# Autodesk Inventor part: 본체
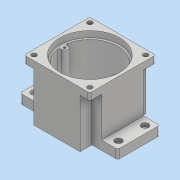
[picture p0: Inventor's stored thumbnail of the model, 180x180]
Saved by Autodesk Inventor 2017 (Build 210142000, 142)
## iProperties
Part Number: 본체
Material: 일반
Document SubType Name: Modeling
Designer: user
Density: 1 g/cm^3
Appearance: 기본값
Mass: 324.711 g
Surface Area: 795.5 cm^2
Volume: 324.711 cm^3
Author: user
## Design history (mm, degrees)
sketch "스케치1"
  geometry: L1 (0, 0)-(140, 0); L2 (0, 0)-(0, 60); L3 (0, 60)-(140, 60); L4 (140, 60)-(140, 0)
  constraints: 8 end point, 1 horizontal, 1 perpendicular, 1 vertical
  dimensions: "d0" = 140 distance of L1.start L1.end; "d4" = 60 distance of L1.start L2.end; "d5" = 140 distance of L2.end L3.end
extrude "돌출1" new body sketch "스케치1" distance "d6" = 13; taper "d7" = 0 deg
sketch "스케치2"
  geometry: L1 (-140, 60)-(0, 60) reference; L2 (-70, 60)-(-70, 0); L3 (0, 0)-(-140, 0) reference; L4 (-140, 30)-(0, 30); L5 (-117, 77)-(-117, -17); L6 (-23, 77)-(-23, -17); L7 (-117, 77)-(-23, 77); L8 (-117, -17)-(-23, -17)
  constraints: 12 end point, 4 parallel, 2 midpoint, 1 horizontal
  dimensions: "d8" = 47 distance between parallel lines of L2 L5; "d9" = 47 distance between parallel lines of L2 L6; "d10" = 47 distance between parallel lines of L4 L7; "d12" = 47 distance between parallel lines of L4 L8
extrude "돌출2" join sketch "스케치2" distance "d13" = 80; taper "d14" = 0 deg
sketch "스케치4"
  geometry: L1 (0, 0)-(-23, 0) reference; L2 (-23, 0)-(-23, -17); L3 (-37, -17)-(-37, 0); L4 (-37, -17)-(-23, -17); L5 (-103, -17)-(-117, -17); L6 (-117, 0)-(-140, 0) reference; L7 (-117, 0)-(-103, 0); L8 (-103, 0)-(-103, -17); L9 (-23, 0)-(-37, 0); L10 (-117, -17)-(-117, 0) reference; L11 (-117, -17)-(-117, 0); L12 (0, 60)-(0, 0) reference; L13 (0, 30)-(-140, 30); L14 (-140, 0)-(-140, 60) reference; L15 (-23, 60)-(-23, 77); L16 (-37, 77)-(-37, 60); L17 (-37, 77)-(-23, 77); L18 (-23, 60)-(-37, 60); L19 (-103, 77)-(-117, 77); L20 (-117, 60)-(-103, 60); L21 (-103, 60)-(-103, 77); L22 (-117, 77)-(-117, 60); L23 (-117, 77)-(-117, 60)
  constraints: 36 end point, 8 symmetric about line, 3 horizontal, 2 midpoint, 2 vertical, 1 collinear
extrude "돌출3" cut sketch "스케치4" distance "d19" = 70; taper "d20" = 0 deg
sketch "스케치7"
  geometry: L1 (37, -17)-(103, -17) reference; L2 (70, -17)-(70, 97.053); L3 (0, 60)-(0, 0) reference; L4 (0, 30)-(150.591, 30); C1 r 43 at (70, 30)
  constraints: 4 end point, 2 midpoint, 2 point on line, 1 centre point, 1 horizontal, 1 vertical
  dimensions: "d26" = 86 diameter of C1
extrude "돌출4" cut sketch "스케치7" distance "d27" = 9; taper "d28" = 0 deg
sketch "스케치8"
  geometry: C1 r 40 at (0, 0); 1 further point
  constraints: 1 centre point
  dimensions: "d29" = 80 diameter of C1
sketch "스케치9"
  geometry: L1 (-117, 77)-(-23, 77) reference; L2 (-70, 77)-(-70, -17); L3 (-23, -17)-(-117, -17) reference; L4 (-140, 0)-(-140, 60) reference; L5 (-140, 30)-(0, 30); L6 (0, 60)-(0, 0) reference; L7 (-70, 30)-(-71, 30); L8 (-70, 30)-(-70, 41); L9 (-70, 30)-(-70, 10); C1 r 27.5 at (-70, 41)
  constraints: 10 end point, 5 midpoint, 3 point on line, 1 centre point, 1 coincident
  dimensions: "d30" = 1 distance of L7.start L7.end; "d31" = 11 distance of L7.start L8.end; "d32" = 20 distance of L7.start L9.end; "d35" = 55 diameter of C1
extrude "돌출5" join sketch "스케치9" distance "d36" = 7; taper "d37" = 0 deg
sketch "스케치10"
  geometry: L1 (-33, 36)-(33, 36) reference; C1 r 27.5 at (0, 0) reference; C2 r 16 at (0, 0); 1 further point
  constraints: 1 centre point, 1 coincident
  dimensions: "d39" = 32 diameter of C2
extrude "돌출6" cut sketch "스케치10" distance "d40" = 8.3; taper "d41" = 0 deg
sketch "스케치11"
  geometry: C1 r 12.5 at (0, 0); 1 further point
  constraints: 1 centre point
  dimensions: "d44" = 25 diameter of C1
extrude "돌출7" cut sketch "스케치11" distance "d45" = 4.7; taper "d46" = 0 deg
sketch "스케치12"
  geometry: C1 r 17.5 at (0, 0); 1 further point
  constraints: 1 centre point
  dimensions: "d47" = 35 diameter of C1
extrude "돌출8" cut sketch "스케치12" distance "d48" = 10; taper "d49" = 0 deg
extrude "돌출9" cut sketch "스케치8" distance "d50" = 62; taper "d51" = 0 deg
node "작업 평면2"
sketch "스케치18"
  geometry: A1 r 40 centre (0, 0) between (-39.279, 7.559) and (-39.279, -7.559) reference; A2 r 4 centre (-36, 0) between (-36.19, -3.995) and (-36.19, 3.995); A3 r 3 centre (-36.333, 6.992) between (-39.279, 7.559) and (-36.19, 3.995); A4 r 3 centre (-36.333, -6.992) between (-36.19, -3.995) and (-39.279, -7.559); A5 r 40 centre (0, 0) between (-39.279, 7.559) and (-39.279, -7.559); 1 further point
  constraints: 10 point on circle, 6 tangent, 4 centre point, 1 horizontal alignment
  dimensions: "d81" = 8 diameter of A2; "d82" = 36 distance of A1.centre A2.centre; "d83" = 3 radius of A3; "d84" = 3 radius of A4
extrude "돌출12" join sketch "스케치18" stored distance "d85" = 7; taper "d86" = 0 deg
sketch "스케치20"
  geometry: L1 (-32, 0)-(-36, 0); A1 r 4 centre (-36, 0) between (-36.19, -3.995) and (-36.19, 3.995) reference; 1 further point
  constraints: 2 end point, 1 horizontal, 1 point on circle
hole "구멍1" sketch "스케치20" at (-36, 0) diameter "d87" = 3.242; stored, may be unused: countersink angle "d91" = 90 deg, drill point angle "d93" = 118 deg; dims "d88" = 7, "d89" = 4, "d90" = 2, "d92" = 9
node "작업 평면1"
chamfer "모따기1" distance "d94" = 0.8; stored, may be unused: second distance "d95" = 2, angle "d96" = 30 deg
sketch "스케치21"
  geometry: C1 r 21 at (0, 11); C2 r 15 at (0, -20); C3 r 17.5 at (0, 11) reference; 1 further point
  constraints: 2 centre point, 1 concentric, 1 vertical alignment
  dimensions: "d97" = 42 diameter of C1; "d98" = 30 diameter of C2; "d101" = 31 distance of C1.centre C2.centre
extrude "돌출13" join sketch "스케치21" distance "d99" = 7; taper "d100" = 0 deg
hole "구멍2" diameter "d104" = 35; stored, may be unused: countersink angle "d108" = 90 deg, drill point angle "d110" = 0 deg; dims "d102" = 10, "d103" = 10, "d105" = 7, "d106" = 4, "d107" = 2, "d109" = 10
hole "구멍3" diameter "d113" = 19; stored, may be unused: countersink angle "d117" = 90 deg, drill point angle "d119" = 0 deg; dims "d111" = 10, "d112" = 10, "d114" = 7, "d115" = 22, "d116" = 7, "d118" = 10
fillet "모깎기1" dims "d120" = 3
chamfer "모따기2" distance "d121" = 1; stored, may be unused: second distance "d122" = 2, angle "d123" = 30 deg
sketch "스케치22"
  geometry: L1 (-117, 77)-(-23, 77) reference; L2 (-70, 77)-(-30, 77); L3 (-23, 77)-(-23, -17) reference; L4 (-23, 30)-(-23, 70); L5 (-23, 70)-(-44.083, 70); L6 (-30, 77)-(-30, 52.8); L7 (-23, 30)-(-140, 30); L8 (-140, 0)-(-140, 60) reference; L9 (-70, 77)-(-70, -17); C1 r 3.5 at (-30, 70); C2 r 3.5 at (-30, -10); C3 r 3.5 at (-110, 70); C4 r 3.5 at (-110, -10); 1 further point
  constraints: 12 end point, 4 centre point, 3 midpoint, 3 point on line, 3 symmetric about line, 2 perpendicular, 2 vertical, 3 other
  dimensions: "d124" = 40 distance of L2.start L2.end; "d125" = 40 distance of L4.start L4.end; "d126" = 7 diameter of C1
extrude "돌출14" cut sketch "스케치22" distance "d127" = 50; taper "d128" = 0 deg
fillet "모깎기2" dims "d129" = 3
sketch "스케치23"
  geometry: L1 (0, 57)-(0, 3) reference; L2 (0, 30)-(0, 49); L3 (0, 49)-(0, 11); L4 (-114, 77)-(-26, 77) reference; L5 (-70, 77)-(-10, 77); L6 (-10, 77)-(-10, -14.148); L7 (0, 49)-(-159.364, 49); L8 (0, 11)-(-172.726, 11); L9 (-70, 77)-(-130, 77); L10 (-130, 77)-(-130, -21.222); C1 r 2.25 at (-130, 49); C2 r 2.25 at (-130, 11); C3 r 2.25 at (-10, 11); C4 r 2.25 at (-10, 49); 1 further point
  constraints: 16 end point, 11 point on line, 4 centre point, 2 horizontal, 2 midpoint, 1 collinear, 1 perpendicular, 1 vertical
  dimensions: "d130" = 19 distance of L2.start L2.end; "d131" = 38 distance of L2.end L3.end; "d132" = 60 distance of L5.start L5.end; "d133" = 60 distance of L5.start L9.end; "d134" = 4.5 diameter of C1; "d135" = 4.5 diameter of C2; "d136" = 4.5 diameter of C3; "d137" = 4.5 diameter of C4
extrude "돌출15" cut sketch "스케치23" distance "d138" = 50; taper "d139" = 0 deg
sketch "스케치24"
  geometry: C1 r 2.25 at (10, 49) reference; C2 r 5 at (10, 49); C3 r 2.25 at (10, 11) reference; C4 r 5 at (10, 11); C5 r 5 at (129.989, 49); C6 r 2.25 at (130, 11) reference; C7 r 5 at (130, 11); 1 further point
  constraints: 4 centre point, 3 coincident
  dimensions: "d140" = 10 diameter of C2; "d141" = 10 diameter of C4; "d142" = 10 diameter of C5; "d143" = 10 diameter of C7
extrude "돌출16" cut sketch "스케치24" distance "d144" = 5; taper "d145" = 0 deg
sketch "스케치25"
  geometry: L1 (77, -80)-(-11, -80) reference; L2 (60.5, 7)-(5.5, 7) reference; L3 (33, -80)-(33, 17.948); 2 further points
  constraints: 2 end point, 1 midpoint, 1 vertical, 1 other
  dimensions: "d146" = 40 distance from line of point (33, -40) L1; "d149" = 0 distance from line of L3 point (33, -40)
feature "엠보싱1" sketch "스케치25" dims "d0" = 140, "d4" = 60, "d5" = 140, "d147" = 0.5, "d148" = 0
node "솔리드1"
mirror "미러1"
